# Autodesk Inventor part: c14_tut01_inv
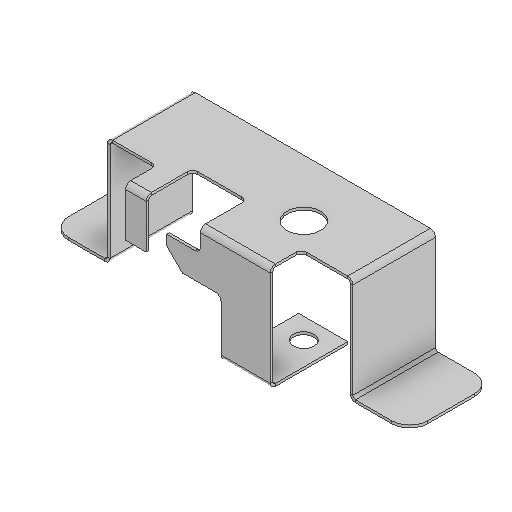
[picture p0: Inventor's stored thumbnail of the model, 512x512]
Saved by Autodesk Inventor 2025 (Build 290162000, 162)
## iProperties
Created: 2015-06
Part Number: c14_tut01_inv
Material: Generic
Document SubType Name: Sheet Metal
Designer: Sandeep
Density: 1 g/cm^3
Sheet Metal Rule: Default_mm
Appearance: Default
Flat Pattern Width: 11.1524 cm
Flat Pattern Length: 21.7129 cm
Flat Pattern Area: 242.15 cm^2
Sheet Metal Width: 111.524 mm
Sheet Metal Length: 217.129 mm
Sheet Metal Area: 24215.030 mm^2
Author: Sandeep
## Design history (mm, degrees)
node "Face1"
  sketch "Sketch1"
    geometry: L1 (0, 12)-(0, 44); L2 (0, 44)-(95, 44); L3 (95, 44)-(95, 12); L4 (95, 12)-(75, 12); L5 (75, 12)-(75, 0); L6 (75, 0)-(48, 0); L7 (48, 0)-(48, 18); L8 (48, 18)-(27, 18); L9 (27, 18)-(27, 0); L10 (27, 0)-(19, 0); L11 (19, 0)-(19, 12); L12 (19, 12)-(0, 12); L13 (0, 0)-(0, 88.508); L14 (0, 0)-(152.255, 0)
    constraints: 28 end point, 11 perpendicular, 4 point on line, 2 vertical, 1 horizontal
    dimensions: "d0" = 26 distance between parallel lines of L2 L8; "d1" = 19 distance between parallel lines of L13 L11; "d2" = 8 distance between parallel lines of L9 L11; "d3" = 32 distance between parallel lines of L12 L2; "d4" = 27 distance between parallel lines of L5 L7; "d5" = 20 distance between parallel lines of L3 L5; "d6" = 95 distance between parallel lines of L1 L3; "d7" = 44 distance between parallel lines of L6 L2
node "Contour Flange1"
node "Contour Flange3"
sketch "Sketch11"
  geometry: L1 (-3.447, 20)-(8, 20); L2 (8, 20)-(8, -8.777); L3 (8, -8.777)-(-3.447, -8.777); L4 (-3.447, -8.777)-(-3.447, 20); L5 (27, 37)-(27, 0) reference; L6 (0, 39)-(-21, 39) reference; 1 further point
  constraints: 8 end point, 2 parallel, 1 horizontal, 1 perpendicular
  dimensions: "d45" = 19 distance between parallel lines of L5 L2; "d104" = 19 distance between parallel lines of L6 L1
cut "Cut1" sketch "Sketch11" dims "d46" = 1 (= Thickness), "d47" = 0
node "Face2"
feature "Corner Round1" dims "d56" = 2
feature "Corner Chamfer1" dims "d57" = 6, "d58" = 6, angle "d59" = 45 deg
node "Flange1"
hole "Hole1" diameter "d72" = 13; stored, may be unused: countersink angle "d76" = 90 deg, drill point angle "d78" = 0 deg; dims "d70" = 9, "d71" = 22, "d73" = 6, "d74" = 4, "d75" = 2, "d77" = 1 (= Thickness)
hole "Hole2" diameter "d81" = 8; stored, may be unused: countersink angle "d85" = 90 deg, drill point angle "d87" = 0 deg; dims "d79" = 9, "d80" = 22, "d82" = 6, "d83" = 4, "d84" = 2, "d86" = 1 (= Thickness)
feature "Corner Round2" dims "d88" = 7
workplane "Work Plane1"
node "Contour Flange4"
  sketch "Sketch15"
    geometry: L1 (0, 0.919)-(0, -40.081); L2 (0, -40.081)-(-22, -40.081); 1 further point
    constraints: 4 end point, 1 perpendicular, 1 vertical
    dimensions: "d90" = 41 distance of L1.start L1.end; "d91" = 22 distance of L1.end L2.end
feature "Corner Round4" dims "d101" = 7
feature "Corner Round5" dims "d102" = 2
body "Solid1"
face "Plate1" dims "d103" = 1 (= Thickness)
sketch "Sketch6"
  geometry: L1 (-75, 1)-(20, 1) reference; L2 (20, 1)-(20, -39); L3 (20, -39)-(42, -39); L4 (-75, 1)-(-75, -39); L5 (-75, -39)-(-97, -39); 1 further point
  constraints: 8 end point, 2 perpendicular, 2 vertical
  dimensions: "d9" = 40 distance of L1.end L2.end; "d10" = 22 distance of L2.end L3.end; "d20" = 40 distance of L1.start L4.end
face "Plate2" dims "d11" = 1 (= BendReliefWidth), "d12" = 0.5 (= BendReliefDepth), "d13" = 2 (= MinimumRemnant), "d14" = 1 (= BendRadius), "d15" = 1 (= BendRadius), "d16" = 1, "d17" = 4 (= CornerReliefSize), "d18" = 1 (= GapSize), "d19" = 1 (= JacobiRadiusSize), "d103" = 1 (= Thickness), "SeamGap" = 0.01
bend "Bend1" dims "d11" = 1 (= BendReliefWidth), "d12" = 0.5 (= BendReliefDepth), "d13" = 2 (= MinimumRemnant), "d14" = 1 (= BendRadius), "d15" = 1 (= BendRadius), "d16" = 1, "d103" = 1 (= Thickness), "SeamGap" = 0.01
feature "Corner1" dims "d16" = 1, "d17" = 4 (= CornerReliefSize), "d18" = 1 (= GapSize), "d19" = 1 (= JacobiRadiusSize)
sketch "Sketch10"
  geometry: L1 (0, 0)-(41, 0); L2 (41, 0)-(41, 30)
  constraints: 4 end point, 1 horizontal, 1 perpendicular
  dimensions: "d42" = 41 distance of L1.start L1.end; "d43" = 30 distance of L1.end L2.end
face "Plate4" dims "d33" = 1 (= BendReliefWidth), "d34" = 0.5 (= BendReliefDepth), "d35" = 2 (= MinimumRemnant), "d36" = 1 (= BendRadius), "d37" = 1 (= BendRadius), "d38" = 1, "d39" = 4 (= CornerReliefSize), "d40" = 1 (= GapSize), "d41" = 1 (= JacobiRadiusSize), "d103" = 1 (= Thickness), "SeamGap" = 0.01
bend "Bend3" dims "d33" = 1 (= BendReliefWidth), "d34" = 0.5 (= BendReliefDepth), "d35" = 2 (= MinimumRemnant), "d36" = 1 (= BendRadius), "d37" = 1 (= BendRadius), "d38" = 1, "d103" = 1 (= Thickness), "SeamGap" = 0.01
feature "Corner3" dims "d38" = 1, "d39" = 4 (= CornerReliefSize), "d40" = 1 (= GapSize), "d41" = 1 (= JacobiRadiusSize)
sketch "Sketch12"
  geometry: L1 (0, -17)-(-13, -17); L2 (-13, -17)-(-13, -7); L3 (-13, -7)-(0, -7); L4 (0, 0)-(0, -17) reference; 1 further point
  constraints: 6 end point, 2 perpendicular, 1 horizontal, 1 point on line
  dimensions: "d54" = 13 distance between parallel lines of L2 L4; "d55" = 10 distance of L1.end L2.end
face "Plate5" dims "d49" = 1 (= BendRadius), "d50" = 1 (= BendReliefWidth), "d52" = 2 (= MinimumRemnant), "d103" = 1 (= Thickness)
bend "Bend4" dims "d49" = 1 (= BendRadius), "d50" = 1 (= BendReliefWidth), "d51" = 0.5 (= BendReliefDepth), "d52" = 2 (= MinimumRemnant), "d53" = 1 (= BendRadius), "d103" = 1 (= Thickness), "SeamGap" = 0.01
sketch "Sketch13"
  geometry: L1 (0, 19)-(-8, 19); L2 (-8, 19)-(-8, 0); 1 other entity
  constraints: 4 end point, 4 other
face "Plate6" dims "d60" = 1 (= BendReliefWidth), "d61" = 0.5 (= BendReliefDepth), "d62" = 2 (= MinimumRemnant), "d63" = 1 (= BendRadius), "d64" = 19, "d65" = 90 deg, "d66" = 1 (= BendRadius), "d67" = 4 (= CornerReliefSize), "d68" = 1 (= GapSize), "d69" = 1 (= JacobiRadiusSize), "d103" = 1 (= Thickness), "SeamGap" = 0.01
bend "Bend5" dims "d60" = 1 (= BendReliefWidth), "d61" = 0.5 (= BendReliefDepth), "d62" = 2 (= MinimumRemnant), "d63" = 1 (= BendRadius), "d64" = 19, "d65" = 90 deg, "d66" = 1 (= BendRadius), "d103" = 1 (= Thickness), "SeamGap" = 0.01
feature "Corner4" dims "d64" = 19, "d65" = 90 deg, "d67" = 4 (= CornerReliefSize), "d68" = 1 (= GapSize), "d69" = 1 (= JacobiRadiusSize)
face "Plate7" dims "d92" = 1 (= BendReliefWidth), "d93" = 0.5 (= BendReliefDepth), "d94" = 2 (= MinimumRemnant), "d95" = 1 (= BendRadius), "d96" = 1 (= BendRadius), "d97" = 1, "d98" = 4 (= CornerReliefSize), "d99" = 1 (= GapSize), "d100" = 1 (= JacobiRadiusSize), "d103" = 1 (= Thickness), "SeamGap" = 0.01
bend "Bend6" dims "d92" = 1 (= BendReliefWidth), "d93" = 0.5 (= BendReliefDepth), "d94" = 2 (= MinimumRemnant), "d95" = 1 (= BendRadius), "d96" = 1 (= BendRadius), "d97" = 1, "d103" = 1 (= Thickness), "SeamGap" = 0.01
feature "Corner5" dims "d97" = 1, "d98" = 4 (= CornerReliefSize), "d99" = 1 (= GapSize), "d100" = 1 (= JacobiRadiusSize)
feature "Definition1"
other parameters: "Thickness" = 1 (derived), "BendRadius" = 1 (= Thickness), "BendReliefWidth" = 1 (= Thickness), "BendReliefDepth" = 0.5 (= 0.5 x Thickness), "CornerReliefSize" = 4 (= 4 x Thickness), "MinimumRemnant" = 2 (= 2 x Thickness), "TransitionRadius" = 1 (= BendRadius), "JacobiRadiusSize" = 1 (= BendRadius), "GapSize" = 1 (= Thickness), "d8" = 1 (= BendRadius), "BendRadius" = 1, "BendReliefDepth" = 0.5, "BendReliefWidth" = 1, "CornerReliefSize" = 4, "GapSize" = 1, "JacobiRadiusSize" = 1, "MinimumRemnant" = 2, "Thickness" = 1, "TransitionRadius" = 1
